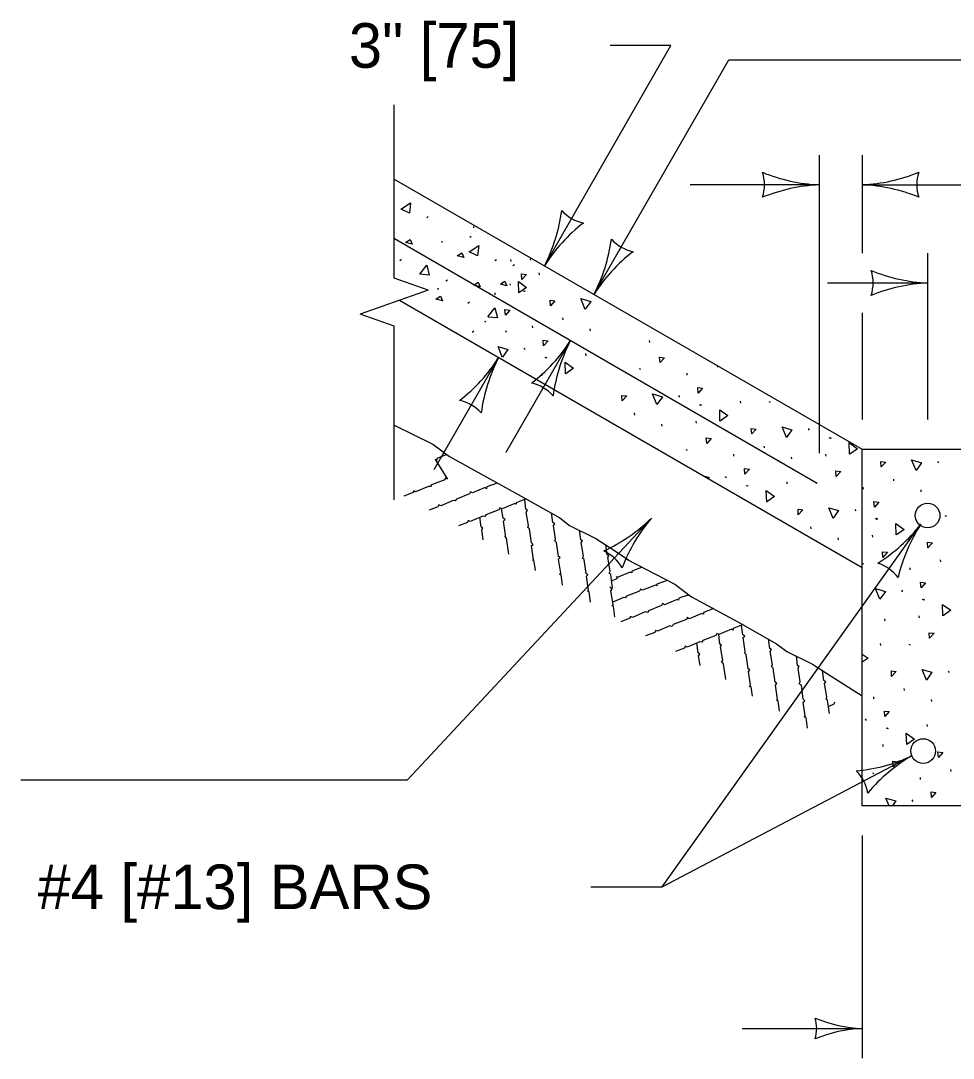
# Model space of a CAD drawing. Extents: x 49991.4 to 50021, y 49987.6 to 50011.4.
# Drawn here: x 50003.894 to 50005.147, y 49992.628 to 49994.022 of the extents above; entities that cross this region are included whole.
import ezdxf

# ---------------------------------------------------------------- set-up
doc = ezdxf.new("R2010")
doc.units = 0
for name, color, linetype in [('Level 1', 7, 'Continuous'), ('Level 2', 7, 'Continuous'), ('Level 3', 7, 'Continuous'), ('Level 6', 7, 'Continuous')]:
    doc.layers.add(name, color=color, linetype=linetype)

msp = doc.modelspace()

# ---------------------------------------------------------------- linework, layer by layer
at = {"layer": 'Level 1'}
for p, q in [((50004.3956, 49993.8094), (50005.025, 49993.4464)), ((50004.4395, 49993.7575), (50004.4416, 49993.759)), ((50004.5024, 49993.7458), (50004.5026, 49993.7438)), ((50004.3963, 49993.7295), (50004.9646, 49993.4009)), ((50004.4599, 49993.726), (50004.46, 49993.7241)), ((50004.4973, 49993.7312), (50004.4994, 49993.7328)), ((50004.4034, 49993.7002), (50004.4055, 49993.7017)), ((50004.5311, 49993.7001), (50004.5332, 49993.7016)), ((50004.5529, 49993.6988), (50004.5527, 49993.7014)), ((50004.5788, 49993.7025), (50004.5789, 49993.7006)), ((50004.5403, 49993.6899), (50004.5402, 49993.6898)), ((50004.5553, 49993.6932), (50004.5574, 49993.6948)), ((50004.5912, 49993.6809), (50004.5909, 49993.6834)), ((50004.4654, 49993.6725), (50004.4675, 49993.674)), ((50004.541, 49993.6714), (50004.5425, 49993.6696)), ((50004.4549, 49993.6627), (50004.454, 49993.6605)), ((50004.5317, 49993.6538), (50004.5315, 49993.6564)), ((50004.5515, 49993.6686), (50004.5516, 49993.6667)), ((50004.5692, 49993.6595), (50004.5709, 49993.6587)), ((50004.5704, 49993.6595), (50004.5721, 49993.6587)), ((50005.025, 49993.2871), (50004.4028, 49993.6465)), ((50004.495, 49993.6428), (50004.4971, 49993.6443)), ((50004.5174, 49993.6186), (50004.5192, 49993.6176)), ((50004.623, 49993.6204), (50004.6227, 49993.6231)), ((50004.5006, 49993.6039), (50004.5027, 49993.6054)), ((50004.5465, 49993.6053), (50004.5456, 49993.6031)), ((50004.5821, 49993.6095), (50004.5819, 49993.6123)), ((50004.6596, 49993.6057), (50004.6594, 49993.6083)), ((50004.7395, 49993.59), (50004.7392, 49993.5927)), ((50004.5702, 49993.5822), (50004.5717, 49993.5803)), ((50004.6538, 49993.5721), (50004.6536, 49993.5749)), ((50004.5984, 49993.5703), (50004.6, 49993.5694)), ((50004.5995, 49993.5703), (50004.6012, 49993.5694)), ((50004.8307, 49993.5568), (50004.8306, 49993.5586)), ((50004.5945, 49993.5451), (50004.5942, 49993.5477)), ((50004.7253, 49993.5547), (50004.7269, 49993.5538)), ((50004.7898, 49993.5459), (50004.7896, 49993.5486)), ((50004.7779, 49993.5185), (50004.7794, 49993.5164)), ((50004.806, 49993.5065), (50004.8079, 49993.5058)), ((50004.8072, 49993.5065), (50004.8091, 49993.5058)), ((50004.8617, 49993.5085), (50004.8614, 49993.5112)), ((50004.8993, 49993.5104), (50004.9011, 49993.5096)), ((50004.7193, 49993.4923), (50004.7191, 49993.4951)), ((50004.7561, 49993.4776), (50004.7558, 49993.4802)), ((50004.8023, 49993.4813), (50004.802, 49993.484)), ((50004.9522, 49993.4741), (50004.9536, 49993.4722)), ((50004.9802, 49993.4622), (50004.982, 49993.4613)), ((50004.9814, 49993.4622), (50004.9832, 49993.4613)), ((50004.7501, 49993.446), (50004.75, 49993.4468)), ((50004.7878, 49993.446), (50004.7897, 49993.4453)), ((50004.8935, 49993.4481), (50004.8931, 49993.4506)), ((50005.025, 49993.2872), (50005.025, 49993.4464)), ((50005.025, 49993.4464), (50005.1847, 49993.4464)), ((50004.8526, 49993.4372), (50004.8524, 49993.4399)), ((50004.9302, 49993.4334), (50004.93, 49993.4359)), ((50004.9765, 49993.437), (50004.9762, 49993.4396)), ((50005.1263, 49993.4299), (50005.1277, 49993.4279)), ((50004.8407, 49993.4098), (50004.8422, 49993.4079)), ((50005.0677, 49993.4037), (50005.0673, 49993.4063)), ((50004.8688, 49993.3978), (50004.8706, 49993.397)), ((50004.87, 49993.3978), (50004.8718, 49993.3971)), ((50004.9243, 49993.3998), (50004.9241, 49993.4025)), ((50004.9621, 49993.4018), (50004.9638, 49993.4009)), ((50005.0268, 49993.3928), (50005.0265, 49993.3954)), ((50005.1044, 49993.3889), (50005.1042, 49993.3916)), ((50005.0149, 49993.3655), (50005.0163, 49993.3635)), ((50005.0429, 49993.3535), (50005.0448, 49993.3526)), ((50005.0441, 49993.3535), (50005.046, 49993.3526)), ((50005.1362, 49993.3574), (50005.1381, 49993.3565)), ((50004.9563, 49993.3394), (50004.9559, 49993.342)), ((50004.993, 49993.3247), (50004.9928, 49993.3272)), ((50005.0392, 49993.3283), (50005.039, 49993.331)), ((50005.0248, 49993.2931), (50005.0267, 49993.2922)), ((50005.1305, 49993.295), (50005.1301, 49993.2978)), ((50005.025, 49992.967), (50005.025, 49993.2872)), ((50005.0896, 49993.2841), (50005.0893, 49993.2869)), ((50005.0777, 49993.2568), (50005.0791, 49993.2548)), ((50005.1057, 49993.2448), (50005.1074, 49993.244)), ((50005.1069, 49993.2448), (50005.1087, 49993.244)), ((50005.0557, 49993.2159), (50005.0555, 49993.2186)), ((50005.102, 49993.2196), (50005.1017, 49993.2223)), ((50005.0499, 49993.1825), (50005.0496, 49993.1852)), ((50005.0876, 49993.1844), (50005.0893, 49993.1835)), ((50005.1404, 49993.1482), (50005.1418, 49993.1462)), ((50005.0407, 49993.1111), (50005.0405, 49993.1138)), ((50005.0817, 49993.122), (50005.0814, 49993.1247)), ((50005.1185, 49993.1072), (50005.1182, 49993.1099)), ((50005.029, 49993.0838), (50005.0304, 49993.0818)), ((50005.057, 49993.0718), (50005.0588, 49993.0709)), ((50005.0583, 49993.0718), (50005.06, 49993.0709)), ((50005.1127, 49993.0739), (50005.1125, 49993.0764)), ((50005.0533, 49993.0466), (50005.0531, 49993.0493)), ((50005.1445, 49993.0134), (50005.1441, 49993.016)), ((50005.0389, 49993.0114), (50005.0406, 49993.0105)), ((50005.1035, 49993.0025), (50005.1033, 49993.0052)), ((50005.0918, 49992.9751), (50005.0932, 49992.9731)), ((50005.1847, 49992.967), (50005.025, 49992.967))]:
    msp.add_line(p, q, dxfattribs=at)
for points in [[(50004.4048, 49993.7692), (50004.4178, 49993.7774), (50004.4164, 49993.7637), (50004.405, 49993.7691)], [(50004.4112, 49993.7242), (50004.4172, 49993.7283), (50004.4199, 49993.7222), (50004.4112, 49993.7242)], [(50004.4964, 49993.7118), (50004.5094, 49993.72), (50004.508, 49993.7063), (50004.4966, 49993.7117)], [(50004.4806, 49993.7061), (50004.4867, 49993.7102), (50004.4893, 49993.7041), (50004.4806, 49993.7061)], [(50004.4301, 49993.6816), (50004.4395, 49993.6937), (50004.4429, 49993.6804), (50004.4304, 49993.6815)], [(50004.5028, 49993.6668), (50004.5088, 49993.6709), (50004.5115, 49993.6648), (50004.5028, 49993.6668)], [(50004.5386, 49993.6681), (50004.5447, 49993.6722), (50004.5473, 49993.6661), (50004.5386, 49993.6681)], [(50004.5634, 49993.6565), (50004.5628, 49993.672), (50004.5739, 49993.6639), (50004.5636, 49993.6566)], [(50004.5675, 49993.6747), (50004.567, 49993.6821), (50004.5736, 49993.6813), (50004.5675, 49993.6747)], [(50004.4519, 49993.648), (50004.458, 49993.6521), (50004.4606, 49993.646), (50004.4519, 49993.648)], [(50004.606, 49993.6393), (50004.6053, 49993.6467), (50004.612, 49993.6459), (50004.606, 49993.6393)], [(50004.6526, 49993.6344), (50004.6469, 49993.6488), (50004.6602, 49993.6451), (50004.6527, 49993.6346)], [(50004.5217, 49993.6242), (50004.5311, 49993.6363), (50004.5345, 49993.623), (50004.522, 49993.6241)], [(50004.5453, 49993.6265), (50004.5447, 49993.6341), (50004.5514, 49993.6332), (50004.5453, 49993.6265)], [(50004.5966, 49993.5854), (50004.5962, 49993.5929), (50004.6028, 49993.592), (50004.5966, 49993.5854)], [(50004.5412, 49993.5702), (50004.5355, 49993.5843), (50004.5487, 49993.5806), (50004.5413, 49993.5703)], [(50004.6261, 49993.5478), (50004.6255, 49993.5633), (50004.6368, 49993.5552), (50004.6264, 49993.5479)], [(50004.7532, 49993.5628), (50004.7525, 49993.5702), (50004.7592, 49993.5693), (50004.7532, 49993.5628)], [(50004.7023, 49993.5113), (50004.7017, 49993.5186), (50004.7084, 49993.518), (50004.7023, 49993.5113)], [(50004.749, 49993.5063), (50004.7431, 49993.5207), (50004.7564, 49993.517), (50004.7491, 49993.5065)], [(50004.8045, 49993.5217), (50004.8039, 49993.5292), (50004.8105, 49993.5283), (50004.8045, 49993.5217)], [(50004.8338, 49993.4841), (50004.8334, 49993.4995), (50004.8445, 49993.4915), (50004.8341, 49993.4842)], [(50004.3956, 49993.4785), (50004.4478, 49993.453), (50004.4703, 49993.4367), (50004.5664, 49993.3834), (50004.6185, 49993.354), (50004.6316, 49993.3438), (50004.6668, 49993.3265), (50004.6919, 49993.3103), (50004.7113, 49993.2974)], [(50004.8765, 49993.467), (50004.8758, 49993.4744), (50004.8825, 49993.4735), (50004.8765, 49993.467)], [(50004.9231, 49993.462), (50004.9173, 49993.4763), (50004.9306, 49993.4725), (50004.9233, 49993.4623)], [(50004.8159, 49993.4542), (50004.8152, 49993.4615), (50004.8218, 49993.4607), (50004.8159, 49993.4542)], [(50005.0081, 49993.4398), (50005.0075, 49993.4553), (50005.0187, 49993.4471), (50005.0084, 49993.4399)], [(50004.4659, 49993.4389), (50004.4532, 49993.4339), (50004.4532, 49993.4318), (50004.4511, 49993.4326), (50004.4675, 49993.4063), (50004.4648, 49993.408), (50004.4637, 49993.4052), (50004.4459, 49993.3984), (50004.4446, 49993.3963), (50004.4419, 49993.3965), (50004.4245, 49993.3893), (50004.4222, 49993.3905), (50004.4212, 49993.388), (50004.409, 49993.3831)], [(50005.0974, 49993.4176), (50005.0914, 49993.4321), (50005.1047, 49993.4283), (50005.0975, 49993.4179)], [(50004.8671, 49993.413), (50004.8667, 49993.4204), (50004.8733, 49993.4196), (50004.8671, 49993.413)], [(50005.0506, 49993.4226), (50005.0501, 49993.4301), (50005.0568, 49993.4292), (50005.0506, 49993.4226)], [(50004.8118, 49993.4104), (50004.8192, 49993.4082), (50004.8181, 49993.4068)], [(50004.9901, 49993.4097), (50004.9895, 49993.4172), (50004.9961, 49993.4164), (50004.9901, 49993.4097)], [(50004.5342, 49993.4009), (50004.5204, 49993.3958), (50004.5201, 49993.3933), (50004.5182, 49993.3949), (50004.501, 49993.3876), (50004.4983, 49993.3892), (50004.4971, 49993.3863), (50004.4795, 49993.3794), (50004.478, 49993.3772), (50004.4753, 49993.3775), (50004.4583, 49993.3705), (50004.4559, 49993.3717), (50004.4545, 49993.3689), (50004.4427, 49993.3646)], [(50004.8966, 49993.3754), (50004.8961, 49993.3909), (50004.9073, 49993.3828), (50004.8969, 49993.3755)], [(50004.5733, 49993.3795), (50004.5599, 49993.3745), (50004.5599, 49993.3724), (50004.5581, 49993.3736), (50004.5408, 49993.3664), (50004.538, 49993.3678), (50004.5366, 49993.3651), (50004.519, 49993.3582), (50004.5177, 49993.3559), (50004.5151, 49993.3564), (50004.498, 49993.3493), (50004.4953, 49993.3507), (50004.4943, 49993.3479), (50004.4823, 49993.3434)], [(50004.5858, 49993.2836), (50004.5842, 49993.2957), (50004.5821, 49993.2966), (50004.5833, 49993.2983), (50004.5805, 49993.3168), (50004.5826, 49993.3185), (50004.5805, 49993.3204), (50004.5776, 49993.3394), (50004.5754, 49993.341), (50004.5765, 49993.3438), (50004.5733, 49993.362), (50004.5752, 49993.364), (50004.573, 49993.3657), (50004.5713, 49993.3786)], [(50005.0414, 49993.3687), (50005.0407, 49993.3761), (50005.0474, 49993.3753), (50005.0414, 49993.3687)], [(50004.55, 49993.3054), (50004.5467, 49993.3268), (50004.5449, 49993.3291), (50004.5456, 49993.3315), (50004.5429, 49993.3499), (50004.5449, 49993.352), (50004.5422, 49993.3537), (50004.5403, 49993.3664)], [(50004.9391, 49993.3582), (50004.9387, 49993.3657), (50004.9453, 49993.3648), (50004.9391, 49993.3582)], [(50004.9859, 49993.3534), (50004.98, 49993.3676), (50004.9933, 49993.3639), (50004.9861, 49993.3535)], [(50004.5155, 49993.3247), (50004.5136, 49993.338), (50004.5151, 49993.3401), (50004.5128, 49993.3419), (50004.5111, 49993.355)], [(50004.6223, 49993.2635), (50004.6203, 49993.2777), (50004.6182, 49993.2786), (50004.6197, 49993.2798), (50004.6168, 49993.2984), (50004.6189, 49993.3008), (50004.6165, 49993.3022), (50004.6139, 49993.3212), (50004.6118, 49993.3232), (50004.6128, 49993.3254), (50004.61, 49993.344), (50004.6117, 49993.3463), (50004.6089, 49993.3477), (50004.6072, 49993.3609)], [(50004.6597, 49993.2407), (50004.6579, 49993.2546), (50004.6555, 49993.2555), (50004.6571, 49993.2569), (50004.6544, 49993.2759), (50004.6563, 49993.2777), (50004.6539, 49993.2793), (50004.6514, 49993.2983), (50004.6491, 49993.3001), (50004.6502, 49993.3028), (50004.6474, 49993.321), (50004.6491, 49993.3232), (50004.6468, 49993.3247), (50004.6449, 49993.3374)], [(50005.0708, 49993.3311), (50005.0703, 49993.3466), (50005.0814, 49993.3384), (50005.071, 49993.3312)], [(50005.1133, 49993.3139), (50005.1128, 49993.3213), (50005.1194, 49993.3205), (50005.1133, 49993.3139)], [(50004.6895, 49993.26), (50004.687, 49993.2778), (50004.6847, 49993.2797), (50004.686, 49993.2824), (50004.6829, 49993.3008), (50004.6845, 49993.3029), (50004.6821, 49993.3045), (50004.6804, 49993.3178)], [(50005.0527, 49993.301), (50005.0522, 49993.3086), (50005.0588, 49993.3078), (50005.0527, 49993.301)], [(50004.7083, 49993.2985), (50004.7729, 49993.2651), (50004.7955, 49993.2482), (50004.858, 49993.2146), (50004.9099, 49993.1847), (50004.9235, 49993.1746), (50004.9583, 49993.1575), (50004.9833, 49993.1412), (50005.025, 49993.1148)], [(50004.729, 49993.2877), (50004.7153, 49993.2827), (50004.7152, 49993.2804), (50004.7129, 49993.2812), (50004.6958, 49993.2741), (50004.6943, 49993.2751)], [(50004.6975, 49993.2741), (50004.696, 49993.2745), (50004.6952, 49993.2721), (50004.6885, 49993.2695)], [(50004.7628, 49993.2701), (50004.7488, 49993.2652), (50004.7488, 49993.2628), (50004.747, 49993.2638), (50004.7295, 49993.2568), (50004.7271, 49993.2585), (50004.7258, 49993.2557), (50004.7081, 49993.2488), (50004.7064, 49993.2465), (50004.704, 49993.2469), (50004.6896, 49993.241)], [(50005.1041, 49993.26), (50005.1035, 49993.2675), (50005.1103, 49993.2666), (50005.1041, 49993.26)], [(50004.6925, 49993.2213), (50004.6908, 49993.2354), (50004.6884, 49993.236), (50004.6901, 49993.2379), (50004.6871, 49993.2561), (50004.6889, 49993.2585), (50004.6867, 49993.26), (50004.6863, 49993.2616)], [(50005.0487, 49993.2447), (50005.0428, 49993.259), (50005.0561, 49993.2552), (50005.0489, 49993.2448)], [(50004.791, 49993.2503), (50004.7783, 49993.246), (50004.7781, 49993.2433), (50004.7763, 49993.2442), (50004.7592, 49993.2374), (50004.7564, 49993.2389), (50004.7554, 49993.2364), (50004.7376, 49993.2293), (50004.7363, 49993.2269), (50004.7334, 49993.2276), (50004.716, 49993.2203), (50004.7136, 49993.2216), (50004.7128, 49993.2192), (50004.7004, 49993.2146)], [(50005.1336, 49993.2224), (50005.133, 49993.2379), (50005.1442, 49993.2299), (50005.1338, 49993.2226)], [(50004.8256, 49993.2321), (50004.8117, 49993.2269), (50004.8117, 49993.2247), (50004.8096, 49993.2255), (50004.7923, 49993.2184), (50004.7898, 49993.22), (50004.7887, 49993.2176), (50004.7708, 49993.2106), (50004.7697, 49993.2079), (50004.7666, 49993.2089), (50004.7496, 49993.2017), (50004.7471, 49993.2027), (50004.7464, 49993.2001), (50004.7338, 49993.1954)], [(50004.8651, 49993.211), (50004.8517, 49993.2055), (50004.8516, 49993.2034), (50004.8495, 49993.2044), (50004.8322, 49993.1973), (50004.8294, 49993.1988), (50004.8284, 49993.1961), (50004.8107, 49993.1894), (50004.8094, 49993.1872), (50004.8067, 49993.1874), (50004.7895, 49993.1804), (50004.7872, 49993.1815), (50004.7859, 49993.1791), (50004.7739, 49993.1743)], [(50004.8774, 49993.1144), (50004.8758, 49993.1268), (50004.8732, 49993.1275), (50004.875, 49993.1292), (50004.872, 49993.1477), (50004.874, 49993.1497), (50004.8715, 49993.151), (50004.8692, 49993.1704), (50004.8671, 49993.1722), (50004.8678, 49993.1746), (50004.8651, 49993.1932), (50004.8671, 49993.1953), (50004.8644, 49993.197), (50004.8627, 49993.2095)], [(50004.8415, 49993.137), (50004.8384, 49993.158), (50004.836, 49993.1601), (50004.8377, 49993.1626), (50004.8345, 49993.1809), (50004.836, 49993.183), (50004.8335, 49993.1843), (50004.8322, 49993.1973)], [(50005.1155, 49993.1925), (50005.115, 49993.1998), (50005.1216, 49993.1991), (50005.1155, 49993.1925)], [(50004.807, 49993.1558), (50004.8048, 49993.1687), (50004.8067, 49993.1709), (50004.8043, 49993.1727), (50004.8025, 49993.1858)], [(50004.9138, 49993.0945), (50004.9119, 49993.1084), (50004.9098, 49993.1093), (50004.9111, 49993.1106), (50004.9084, 49993.1293), (50004.9103, 49993.1316), (50004.9082, 49993.1335), (50004.9051, 49993.1521), (50004.903, 49993.1544), (50004.9044, 49993.1564), (50004.9014, 49993.175), (50004.903, 49993.1772), (50004.9008, 49993.1787), (50004.8988, 49993.1916)], [(50004.9514, 49993.0713), (50004.9495, 49993.0857), (50004.947, 49993.0863), (50004.9484, 49993.0882), (50004.9456, 49993.1066), (50004.9479, 49993.1084), (50004.9455, 49993.1104), (50004.9432, 49993.1292), (50004.9404, 49993.1311), (50004.9418, 49993.1337), (50004.9389, 49993.152), (50004.9404, 49993.1543), (50004.938, 49993.1558), (50004.9365, 49993.1686)], [(50005.025, 49993.171), (50005.0328, 49993.1654), (50005.025, 49993.16)], [(50004.9809, 49993.0912), (50004.9784, 49993.1092), (50004.9765, 49993.1106), (50004.9774, 49993.1135), (50004.9743, 49993.1316), (50004.9762, 49993.1337), (50004.9736, 49993.1355), (50004.9718, 49993.1489)], [(50005.0646, 49993.1409), (50005.0642, 49993.1484), (50005.0708, 49993.1476), (50005.0646, 49993.1409)], [(50005.1115, 49993.136), (50005.1055, 49993.1504), (50005.1188, 49993.1466), (50005.1116, 49993.1362)], [(50004.9888, 49993.1054), (50004.9875, 49993.1058), (50004.9867, 49993.1035), (50004.9801, 49993.1006)], [(50005.0555, 49993.0871), (50005.0548, 49993.0945), (50005.0614, 49993.0937), (50005.0555, 49993.0871)], [(50005.0848, 49993.0494), (50005.0843, 49993.0649), (50005.0955, 49993.0567), (50005.0851, 49993.0495)], [(50005.1274, 49993.0322), (50005.1267, 49993.0397), (50005.1335, 49993.0389), (50005.1274, 49993.0322)], [(50005.0668, 49993.0194), (50005.0661, 49993.0269), (50005.073, 49993.026), (50005.0668, 49993.0194)], [(50005.1181, 49992.9784), (50005.1176, 49992.9858), (50005.1242, 49992.9849), (50005.1181, 49992.9784)], [(50005.0611, 49992.967), (50005.0569, 49992.9773), (50005.0702, 49992.9736), (50005.0656, 49992.967)]]:
    msp.add_lwpolyline(points, dxfattribs=at)
for centre in [(50005.1129, 49993.3573), (50005.107, 49993.0407)]:
    msp.add_circle(centre, 0.0166, dxfattribs=at)
at = {"layer": 'Level 3'}
for p, q in [((50004.5978, 49993.6928), (50004.7676, 49993.9891)), ((50004.7676, 49993.9891), (50004.686, 49993.9891)), ((50004.6644, 49993.6544), (50004.8459, 49993.9697)), ((50004.8459, 49993.9697), (50005.4057, 49993.9697)), ((50004.967, 49993.8418), (50004.967, 49993.4409)), ((50005.025, 49993.8418), (50005.025, 49993.7099)), ((50004.967, 49993.8018), (50004.7936, 49993.8018)), ((50005.025, 49993.8018), (50005.4057, 49993.8018)), ((50005.1131, 49993.4864), (50005.1131, 49993.7099)), ((50004.9782, 49993.6699), (50005.1131, 49993.6699)), ((50005.025, 49993.6299), (50005.025, 49993.4864)), ((50004.5462, 49993.4424), (50004.633, 49993.5926)), ((50004.4495, 49993.4192), (50004.5362, 49993.5694)), ((50004.4137, 49993.0018), (50004.7417, 49993.3539)), ((50004.7562, 49992.8582), (50005.1037, 49993.3455)), ((50004.7562, 49992.8582), (50005.0921, 49993.0345)), ((50003.8938, 49993.0018), (50004.4137, 49993.0018)), ((50005.025, 49992.927), (50005.025, 49992.6278)), ((50004.6603, 49992.8582), (50004.7562, 49992.8582)), ((50004.8638, 49992.6678), (50005.025, 49992.6678))]:
    msp.add_line(p, q, dxfattribs=at)
for centre, radius, start, end in [((50004.9762, 49994.0239), 0.2223, 247.456, 267.6395), ((50004.8388, 49993.8018), 0.0548, 342.1388, 17.8612), ((50005.0135, 49994.0345), 0.233, 272.8273, 292.0772), ((50005.1532, 49993.8018), 0.0548, 162.1388, 197.8612), ((50004.9785, 49993.5691), 0.233, 92.8273, 112.0772), ((50005.0158, 49993.5797), 0.2223, 67.456, 87.6395), ((50004.3902, 49993.7985), 0.233, 333.0144, 352.2643), ((50004.6616, 49993.804), 0.0548, 222.3259, 258.0483), ((50004.786, 49993.5744), 0.2223, 127.6431, 147.8266), ((50004.457, 49993.7605), 0.233, 332.8963, 352.1462), ((50004.7284, 49993.7655), 0.0548, 222.2078, 257.9302), ((50004.8523, 49993.5356), 0.2223, 127.525, 147.7085), ((50005.1223, 49993.892), 0.2223, 247.456, 267.6395), ((50004.9849, 49993.6699), 0.0548, 342.1388, 17.8612), ((50005.1246, 49993.4372), 0.233, 92.8273, 112.0772), ((50004.4452, 49993.7116), 0.2223, 307.4511, 327.6346), ((50004.8402, 49993.4862), 0.233, 152.8224, 172.0722), ((50004.3484, 49993.6884), 0.2223, 307.4724, 327.6559), ((50004.7435, 49993.4631), 0.233, 152.8437, 172.0936), ((50004.5689, 49993.4816), 0.0548, 42.1339, 77.8563), ((50004.4721, 49993.4584), 0.0548, 42.1552, 77.8776), ((50004.5854, 49993.512), 0.2223, 294.4876, 314.6711), ((50004.9198, 49993.2037), 0.233, 139.8589, 159.1087), ((50004.9282, 49993.4819), 0.2223, 301.9618, 322.1454), ((50005.2998, 49993.2197), 0.233, 147.3331, 166.583), ((50004.6543, 49993.2601), 0.0548, 29.1704, 64.8928), ((50005.0293, 49993.2411), 0.0548, 36.6447, 72.367), ((50004.9969, 49993.2354), 0.2223, 275.1536, 295.3371), ((50005.2104, 49992.8338), 0.233, 120.5249, 139.7748), ((50004.9785, 49992.9749), 0.0548, 9.8364, 45.5588), ((50005.0326, 49992.8529), 0.1853, 247.456, 267.6395), ((50004.9182, 49992.6678), 0.0456, 342.1388, 17.8612), ((50005.0346, 49992.4739), 0.1942, 92.8273, 112.0772)]:
    msp.add_arc(centre, radius, start, end, dxfattribs=at)
at = {"layer": 'Level 6'}
for p, q in [((50004.3956, 49993.6764), (50004.3956, 49993.9094)), ((50004.4413, 49993.6602), (50004.3956, 49993.6764)), ((50004.4413, 49993.6602), (50004.3956, 49993.644)), ((50004.3956, 49993.644), (50004.3499, 49993.6278)), ((50004.3956, 49993.6116), (50004.3499, 49993.6278)), ((50004.3956, 49993.3785), (50004.3956, 49993.6116))]:
    msp.add_line(p, q, dxfattribs=at)

# ---------------------------------------------------------------- texts
at = {"layer": 'Level 2'}
for s, p in [('3" [75]', (50004.3349, 49993.9591)), ('#4 [#13] BARS', (50003.9164, 49992.8282))]:
    msp.add_text(s, height=0.06, dxfattribs=at).set_placement(p)

doc.saveas('drawing.dxf')
